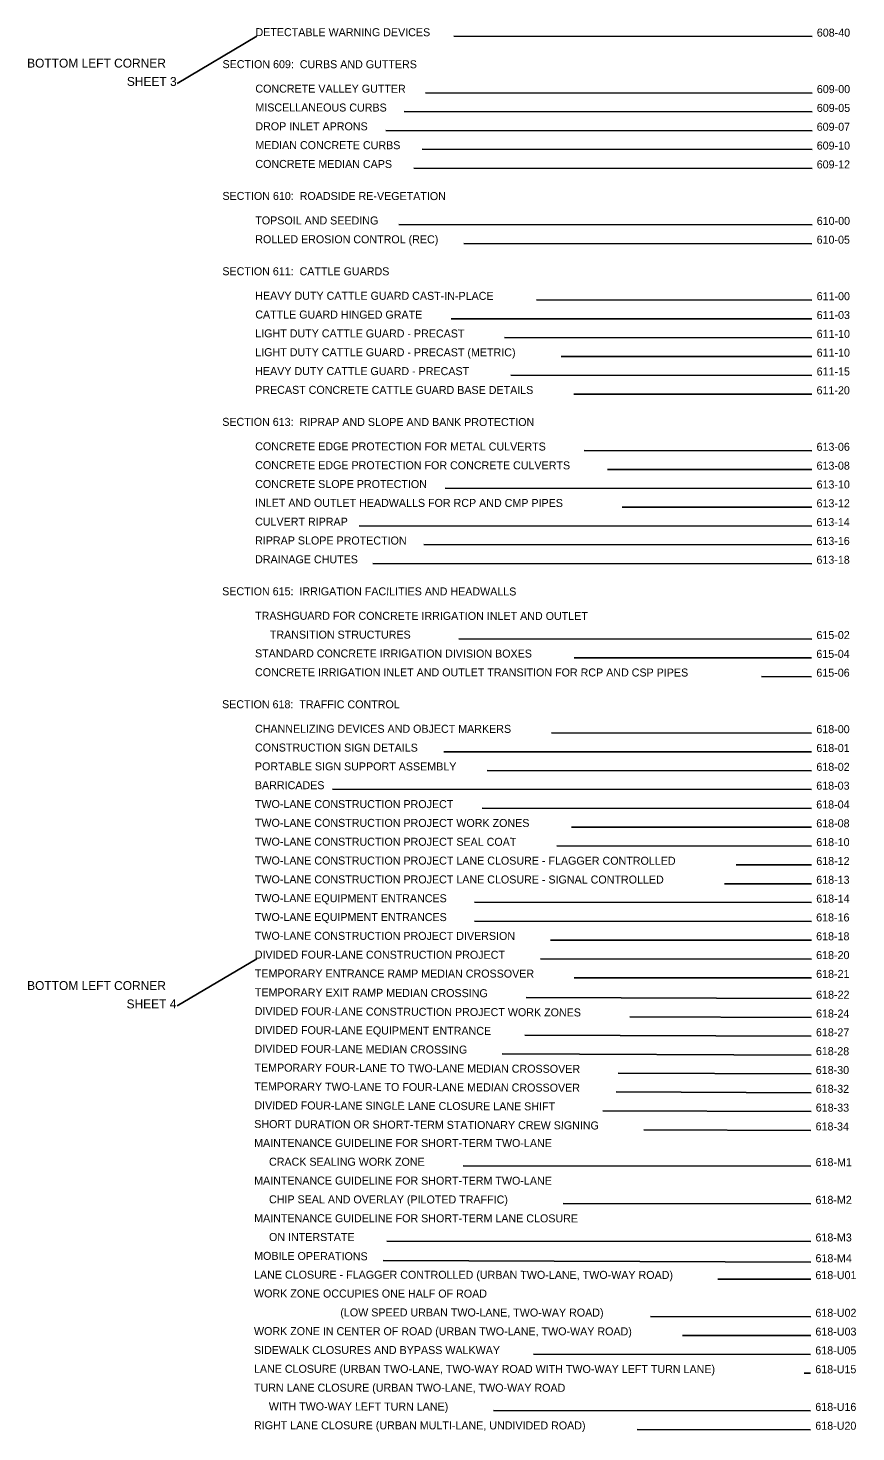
# Model space of a CAD drawing. Extents: x 49987.3 to 50007.6, y 49951 to 50011.
# Drawn here: x 49998.75 to 50007.55, y 49966.14 to 49981.05 of the extents above; entities that cross this region are included whole.
import ezdxf

# ---------------------------------------------------------------- set-up
doc = ezdxf.new("R2010")
doc.units = 0
doc.layers.add('Default', color=7, linetype='Continuous')
doc.layers.add('Level 1', color=7, linetype='Continuous')

msp = doc.modelspace()

# ---------------------------------------------------------------- linework, layer by layer
at = {"layer": 'Default'}
for p, q in [((50001.184, 49980.963), (50000.336, 49980.462)), ((50000.336, 49980.462), (50000.336, 49980.462)), ((50001.184, 49971.163), (50000.336, 49970.662)), ((50000.336, 49970.662), (50000.336, 49970.662))]:
    msp.add_line(p, q, dxfattribs=at)
at = {"layer": 'Level 1'}
for p, q in [((50003.278, 49980.965), (50007.085, 49980.962)), ((50002.975, 49980.363), (50007.085, 49980.36)), ((50002.749, 49980.164), (50007.085, 49980.16)), ((50002.555, 49979.964), (50007.084, 49979.96)), ((50002.94, 49979.763), (50007.084, 49979.76)), ((50002.853, 49979.563), (50007.084, 49979.56)), ((50002.692, 49978.964), (50007.084, 49978.96)), ((50003.385, 49978.763), (50007.083, 49978.76)), ((50004.157, 49978.162), (50007.083, 49978.16)), ((50003.248, 49977.963), (50007.083, 49977.96)), ((50003.815, 49977.763), (50007.083, 49977.76)), ((50004.419, 49977.562), (50007.083, 49977.56)), ((50003.882, 49977.363), (50007.083, 49977.36)), ((50004.553, 49977.162), (50007.082, 49977.16)), ((50004.662, 49976.562), (50007.082, 49976.56)), ((50004.91, 49976.362), (50007.082, 49976.36)), ((50003.186, 49976.163), (50007.082, 49976.16)), ((50005.065, 49975.962), (50007.082, 49975.96)), ((50002.27, 49975.764), (50007.081, 49975.76)), ((50002.96, 49975.563), (50007.081, 49975.56)), ((50002.415, 49975.364), (50007.081, 49975.36)), ((50003.331, 49974.563), (50007.081, 49974.56)), ((50004.556, 49974.362), (50007.08, 49974.36)), ((50006.547, 49974.161), (50007.08, 49974.16)), ((50004.315, 49973.562), (50007.08, 49973.56)), ((50003.17, 49973.363), (50007.08, 49973.36)), ((50003.63, 49973.163), (50007.08, 49973.16)), ((50001.986, 49972.964), (50007.079, 49972.96)), ((50003.578, 49972.763), (50007.079, 49972.76)), ((50004.527, 49972.562), (50007.079, 49972.56)), ((50004.373, 49972.362), (50007.079, 49972.36)), ((50006.279, 49972.161), (50007.079, 49972.16)), ((50006.154, 49971.961), (50007.079, 49971.96)), ((50003.496, 49971.763), (50007.079, 49971.76)), ((50003.496, 49971.563), (50007.078, 49971.56)), ((50004.304, 49971.362), (50007.078, 49971.36)), ((50004.199, 49971.162), (50007.078, 49971.16)), ((50004.556, 49970.962), (50007.078, 49970.96)), ((50004.045, 49970.753), (50007.078, 49970.74)), ((50005.146, 49970.548), (50007.077, 49970.54)), ((50004.033, 49970.353), (50007.076, 49970.34)), ((50003.792, 49970.154), (50007.075, 49970.14)), ((50005.025, 49969.948), (50007.074, 49969.94)), ((50005.004, 49969.748), (50007.074, 49969.74)), ((50004.861, 49969.549), (50007.074, 49969.54)), ((50005.298, 49969.347), (50007.072, 49969.34)), ((50003.376, 49968.963), (50007.072, 49968.96)), ((50004.44, 49968.562), (50007.071, 49968.56)), ((50002.564, 49968.164), (50007.071, 49968.16)), ((50002.527, 49967.959), (50007.071, 49967.94)), ((50006.082, 49967.761), (50007.07, 49967.76)), ((50005.367, 49967.362), (50007.07, 49967.36)), ((50005.709, 49967.161), (50007.07, 49967.16)), ((50004.123, 49966.963), (50007.069, 49966.96)), ((50007, 49966.76), (50007.069, 49966.76)), ((50003.697, 49966.363), (50007.069, 49966.36)), ((50005.227, 49966.162), (50007.069, 49966.16))]:
    msp.add_line(p, q, dxfattribs=at)

# ---------------------------------------------------------------- texts
at = {"layer": 'Default'}
for s, p in [('BOTTOM LEFT CORNER ', (49998.742, 49980.631)), ('SHEET 3', (49999.802, 49980.436)), ('BOTTOM LEFT CORNER ', (49998.742, 49970.831)), ('SHEET 4', (49999.799, 49970.636))]:
    msp.add_text(s, height=0.095, dxfattribs=at).set_placement(p)
at = {"layer": 'Level 1'}
for s, rotation, p in [('DETECTABLE WARNING DEVICES', 359.9586, (50001.169, 49980.965)), ('608-40', 359.9586, (50007.135, 49980.96)), ('SECTION 609:  CURBS AND GUTTERS', 359.9586, (50000.819, 49980.625)), ('CONCRETE VALLEY GUTTER', 359.9586, (50001.168, 49980.365)), ('609-00', 359.9586, (50007.135, 49980.36)), ('MISCELLANEOUS CURBS', 359.9586, (50001.168, 49980.165)), ('609-05', 359.9586, (50007.135, 49980.16)), ('DROP INLET APRONS', 359.9586, (50001.168, 49979.965)), ('609-07', 359.9586, (50007.134, 49979.96)), ('MEDIAN CONCRETE CURBS', 359.9586, (50001.168, 49979.765)), ('609-10', 359.9586, (50007.134, 49979.76)), ('CONCRETE MEDIAN CAPS', 359.9586, (50001.168, 49979.565)), ('609-12', 359.9586, (50007.134, 49979.56)), ('SECTION 610:  ROADSIDE RE-VEGETATION', 359.9586, (50000.818, 49979.225)), ('TOPSOIL AND SEEDING', 359.9586, (50001.167, 49978.965)), ('610-00', 359.9586, (50007.134, 49978.96)), ('ROLLED EROSION CONTROL (REC)', 359.9586, (50001.167, 49978.765)), ('610-05', 359.9586, (50007.133, 49978.76)), ('SECTION 611:  CATTLE GUARDS', 359.9586, (50000.817, 49978.425)), ('HEAVY DUTY CATTLE GUARD CAST-IN-PLACE', 359.9586, (50001.167, 49978.165)), ('611-00', 359.9586, (50007.133, 49978.16)), ('CATTLE GUARD HINGED GRATE', 359.9586, (50001.167, 49977.965)), ('611-03', 359.9586, (50007.133, 49977.96)), ('LIGHT DUTY CATTLE GUARD - PRECAST', 359.9586, (50001.167, 49977.765)), ('611-10', 359.9586, (50007.133, 49977.76)), ('LIGHT DUTY CATTLE GUARD - PRECAST (METRIC)', 359.9586, (50001.167, 49977.565)), ('611-10', 359.9586, (50007.133, 49977.56)), ('HEAVY DUTY CATTLE GUARD - PRECAST', 359.9586, (50001.166, 49977.365)), ('611-15', 359.9586, (50007.133, 49977.36)), ('PRECAST CONCRETE CATTLE GUARD BASE DETAILS', 359.9586, (50001.166, 49977.165)), ('611-20', 359.9586, (50007.132, 49977.16)), ('SECTION 613:  RIPRAP AND SLOPE AND BANK PROTECTION', 359.9586, (50000.816, 49976.825)), ('CONCRETE EDGE PROTECTION FOR METAL CULVERTS', 359.9586, (50001.166, 49976.565)), ('613-06', 359.9586, (50007.132, 49976.56)), ('CONCRETE EDGE PROTECTION FOR CONCRETE CULVERTS', 359.9586, (50001.166, 49976.365)), ('613-08', 359.9586, (50007.132, 49976.36)), ('CONCRETE SLOPE PROTECTION', 359.9586, (50001.166, 49976.165)), ('613-10', 359.9586, (50007.132, 49976.16)), ('INLET AND OUTLET HEADWALLS FOR RCP AND CMP PIPES', 359.9586, (50001.165, 49975.965)), ('613-12', 359.9586, (50007.132, 49975.96)), ('CULVERT RIPRAP', 359.9586, (50001.165, 49975.765)), ('613-14', 359.9586, (50007.131, 49975.76)), ('RIPRAP SLOPE PROTECTION      ', 359.9586, (50001.165, 49975.565)), ('613-16', 359.9586, (50007.131, 49975.56)), ('DRAINAGE CHUTES', 359.9586, (50001.165, 49975.365)), ('613-18', 359.9586, (50007.131, 49975.36)), ('SECTION 615:  IRRIGATION FACILITIES AND HEADWALLS', 359.9586, (50000.815, 49975.025)), ('TRASHGUARD FOR CONCRETE IRRIGATION INLET AND OUTLET ', 359.9586, (50001.165, 49974.765)), ('     TRANSITION STRUCTURES', 359.9586, (50001.164, 49974.565)), ('615-02', 359.9586, (50007.131, 49974.56)), ('STANDARD CONCRETE IRRIGATION DIVISION BOXES', 359.9586, (50001.164, 49974.365)), ('615-04', 359.9586, (50007.13, 49974.36)), ('CONCRETE IRRIGATION INLET AND OUTLET TRANSITION FOR RCP AND CSP PIPES', 359.9586, (50001.164, 49974.165)), ('615-06', 359.9586, (50007.13, 49974.16)), ('SECTION 618:  TRAFFIC CONTROL', 359.9586, (50000.814, 49973.825)), ('CHANNELIZING DEVICES AND OBJECT MARKERS            ', 359.9586, (50001.164, 49973.565)), ('618-00', 359.9586, (50007.13, 49973.56)), ('CONSTRUCTION SIGN DETAILS', 359.9586, (50001.164, 49973.365)), ('618-01', 359.9586, (50007.13, 49973.36)), ('PORTABLE SIGN SUPPORT ASSEMBLY', 359.9586, (50001.163, 49973.165)), ('618-02', 359.9586, (50007.13, 49973.16)), ('BARRICADES                    ', 359.9586, (50001.163, 49972.965)), ('618-03', 359.9586, (50007.129, 49972.96)), ('TWO-LANE CONSTRUCTION PROJECT', 359.9586, (50001.163, 49972.765)), ('618-04', 359.9586, (50007.129, 49972.76)), ('TWO-LANE CONSTRUCTION PROJECT WORK ZONES ', 359.9586, (50001.163, 49972.565)), ('618-08', 359.9586, (50007.129, 49972.56)), ('TWO-LANE CONSTRUCTION PROJECT SEAL COAT', 359.9586, (50001.163, 49972.365)), ('618-10', 359.9586, (50007.129, 49972.36)), ('TWO-LANE CONSTRUCTION PROJECT LANE CLOSURE - FLAGGER CONTROLLED', 359.9586, (50001.163, 49972.165)), ('618-12', 359.9586, (50007.129, 49972.16)), ('TWO-LANE CONSTRUCTION PROJECT LANE CLOSURE - SIGNAL CONTROLLED', 359.9586, (50001.163, 49971.965)), ('618-13', 359.9586, (50007.129, 49971.96)), ('TWO-LANE EQUIPMENT ENTRANCES', 359.9586, (50001.162, 49971.765)), ('618-14', 359.9586, (50007.129, 49971.76)), ('TWO-LANE EQUIPMENT ENTRANCES ', 359.9586, (50001.162, 49971.565)), ('618-16', 359.9586, (50007.128, 49971.56)), ('TWO-LANE CONSTRUCTION PROJECT DIVERSION', 359.9586, (50001.162, 49971.365)), ('618-18', 359.9586, (50007.128, 49971.36)), ('DIVIDED FOUR-LANE CONSTRUCTION PROJECT', 359.9586, (50001.162, 49971.165)), ('618-20', 359.9586, (50007.128, 49971.16)), ('TEMPORARY ENTRANCE RAMP MEDIAN CROSSOVER', 359.9586, (50001.162, 49970.965)), ('618-21', 359.9586, (50007.128, 49970.96)), ('TEMPORARY EXIT RAMP MEDIAN CROSSING', 359.7586, (50001.162, 49970.765)), ('618-22', 359.7586, (50007.128, 49970.74)), ('DIVIDED FOUR-LANE CONSTRUCTION PROJECT WORK ZONES', 359.7586, (50001.161, 49970.565)), ('618-24', 359.7586, (50007.127, 49970.54)), ('DIVIDED FOUR-LANE EQUIPMENT ENTRANCE', 359.7586, (50001.16, 49970.365)), ('618-27', 359.7586, (50007.126, 49970.34)), ('DIVIDED FOUR-LANE MEDIAN CROSSING', 359.7586, (50001.159, 49970.165)), ('618-28', 359.7586, (50007.125, 49970.14)), ('TEMPORARY FOUR-LANE TO TWO-LANE MEDIAN CROSSOVER', 359.7586, (50001.158, 49969.965)), ('618-30', 359.7586, (50007.124, 49969.94)), ('TEMPORARY TWO-LANE TO FOUR-LANE MEDIAN CROSSOVER', 359.7586, (50001.157, 49969.765)), ('618-32', 359.7586, (50007.124, 49969.74)), ('DIVIDED FOUR-LANE SINGLE LANE CLOSURE LANE SHIFT     ', 359.7586, (50001.157, 49969.565)), ('618-33', 359.7586, (50007.124, 49969.54)), ('SHORT DURATION OR SHORT-TERM STATIONARY CREW SIGNING', 359.7586, (50001.156, 49969.365)), ('618-34', 359.7586, (50007.122, 49969.34)), ('MAINTENANCE GUIDELINE FOR SHORT-TERM TWO-LANE', 359.9586, (50001.155, 49969.165)), ('     CRACK SEALING WORK ZONE', 359.9586, (50001.155, 49968.965)), ('618-M1', 359.9586, (50007.122, 49968.96)), ('MAINTENANCE GUIDELINE FOR SHORT-TERM TWO-LANE', 359.9586, (50001.155, 49968.765)), ('     CHIP SEAL AND OVERLAY (PILOTED TRAFFIC)', 359.9586, (50001.155, 49968.565)), ('618-M2', 359.9586, (50007.121, 49968.56)), ('MAINTENANCE GUIDELINE FOR SHORT-TERM LANE CLOSURE', 359.9586, (50001.155, 49968.365)), ('     ON INTERSTATE', 359.9586, (50001.155, 49968.165)), ('618-M3', 359.9586, (50007.121, 49968.16)), ('MOBILE OPERATIONS', 359.7586, (50001.155, 49967.965)), ('618-M4', 359.7586, (50007.121, 49967.94)), ('LANE CLOSURE - FLAGGER CONTROLLED (URBAN TWO-LANE, TWO-WAY ROAD)', 359.9586, (50001.154, 49967.765)), ('618-U01', 359.9586, (50007.12, 49967.76)), ('WORK ZONE OCCUPIES ONE HALF OF ROAD', 359.9586, (50001.154, 49967.565)), ('     (LOW SPEED URBAN TWO-LANE, TWO-WAY ROAD)', 359.9586, (50001.913, 49967.364)), ('618-U02', 359.9586, (50007.12, 49967.36)), ('WORK ZONE IN CENTER OF ROAD (URBAN TWO-LANE, TWO-WAY ROAD)', 359.9586, (50001.153, 49967.165)), ('618-U03', 359.9586, (50007.12, 49967.16)), ('SIDEWALK CLOSURES AND BYPASS WALKWAY', 359.9586, (50001.153, 49966.965)), ('618-U05', 359.9586, (50007.119, 49966.96)), ('LANE CLOSURE (URBAN TWO-LANE, TWO-WAY ROAD WITH TWO-WAY LEFT TURN LANE)', 359.9586, (50001.153, 49966.765)), ('618-U15', 359.9586, (50007.119, 49966.76)), ('TURN LANE CLOSURE (URBAN TWO-LANE, TWO-WAY ROAD ', 359.9586, (50001.153, 49966.565)), ('     WITH TWO-WAY LEFT TURN LANE)', 359.9586, (50001.153, 49966.365)), ('618-U16', 359.9586, (50007.119, 49966.36)), ('RIGHT LANE CLOSURE (URBAN MULTI-LANE, UNDIVIDED ROAD)', 359.9586, (50001.153, 49966.165)), ('618-U20', 359.9586, (50007.119, 49966.16))]:
    msp.add_text(s, height=0.085, rotation=rotation, dxfattribs=at).set_placement(p)

doc.saveas('drawing.dxf')
